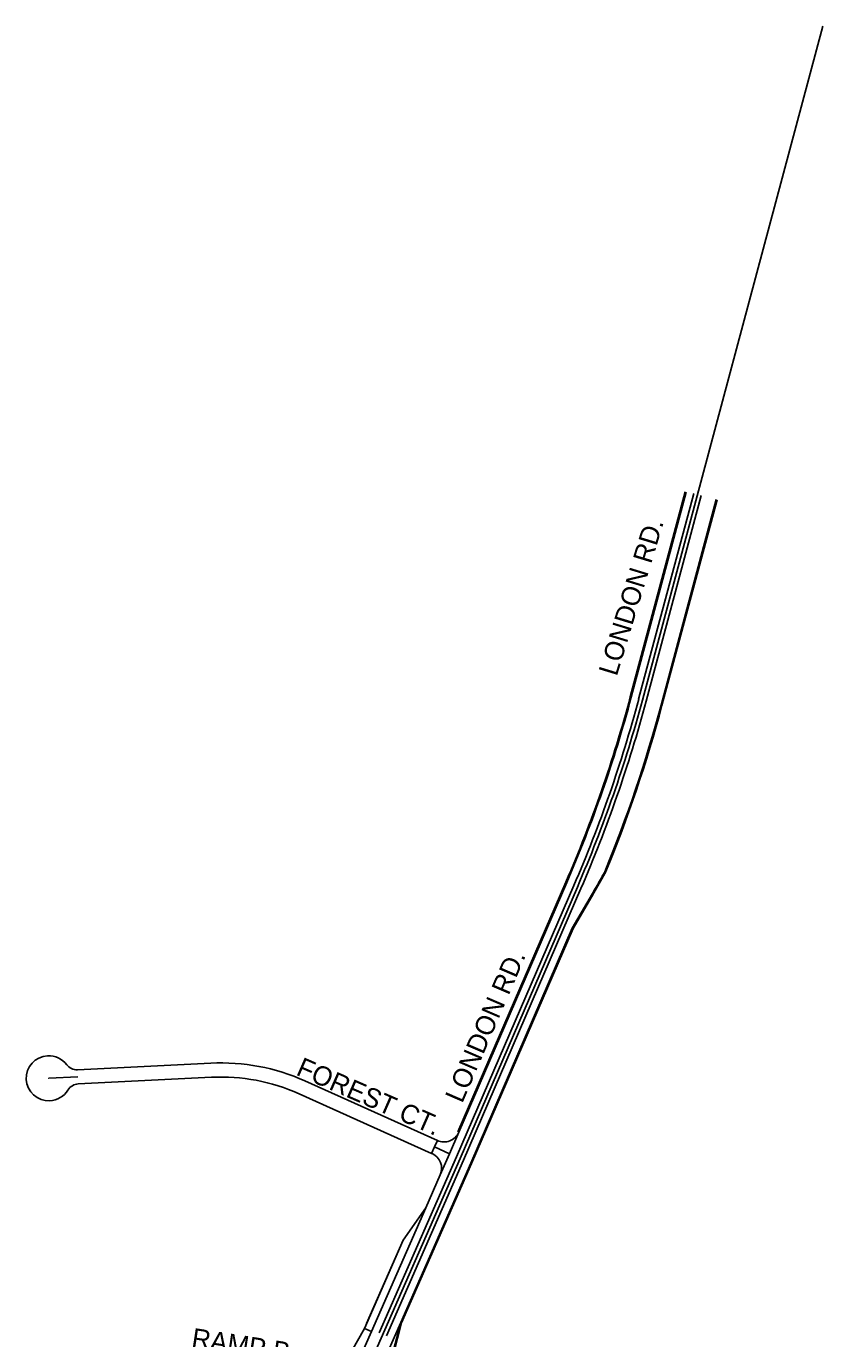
# Model space of a CAD drawing. Extents: x 2315515 to 2326910, y 758186 to 762794.
# Drawn here: x 2320679 to 2321918, y 760752 to 762794 of the extents above; entities that cross this region are included whole.
import ezdxf

# ---------------------------------------------------------------- set-up
doc = ezdxf.new("R2010")
doc.units = 0
for name, color, linetype in [('Default', 7, 'Continuous'), ('Draft_Corr_Range_Design', 7, 'Continuous'), ('E_Terrain_Exterior', 7, 'Continuous'), ('Pavement Marking Yellow', 7, 'Continuous'), ('Road_Curb_Face', 7, 'Continuous'), ('TL_End Condition Ditch In', 7, 'Continuous'), ('TL_End Condition Ditch Out', 7, 'Continuous'), ('TL_Pavement Edge Sub', 7, 'Continuous')]:
    doc.layers.add(name, color=color, linetype=linetype)

msp = doc.modelspace()

# ---------------------------------------------------------------- linework, layer by layer
at = {"layer": 'Default'}
for p, q in [((2321637, 761745.2), (2321917.6, 762793.6)), ((2321637, 761745.2), (2321917.6, 762793.6)), ((2321637, 761745.2), (2321917.6, 762793.6)), ((2321353.4, 761032.3), (2321535.9, 761454.5)), ((2321353.4, 761032.3), (2321535.9, 761454.5)), ((2321353.4, 761032.3), (2321535.9, 761454.5)), ((2320896.6, 759992.2), (2321353.4, 761032.3)), ((2320896.6, 759992.2), (2321353.4, 761032.3)), ((2320896.6, 759992.2), (2321353.4, 761032.3))]:
    msp.add_line(p, q, dxfattribs=at)
msp.add_arc((2319608.4, 762288), 2100, 336.617, 345.0204, dxfattribs=at)
msp.add_arc((2319608.4, 762288), 2100, 336.617, 345.0204, dxfattribs=at)
msp.add_arc((2319608.4, 762288), 2100, 336.617, 345.0204, dxfattribs=at)
msp.add_open_spline([(2321559.3, 761444.4), (2321559.6, 761445), (2321560.3, 761446.1), (2321561.2, 761447.8), (2321562.2, 761449.5), (2321563.2, 761451.2), (2321564.1, 761452.9), (2321565.1, 761454.5), (2321566.1, 761456.2), (2321567, 761457.9), (2321568, 761459.6), (2321569, 761461.3), (2321569.9, 761463), (2321570.9, 761464.7), (2321571.8, 761466.4), (2321572.8, 761468.1), (2321573.7, 761469.7), (2321574.7, 761471.4), (2321575.6, 761473.1), (2321576.6, 761474.8), (2321577.5, 761476.5), (2321578.2, 761477.7), (2321578.5, 761478.2)], degree=3, dxfattribs=at)
at = {"layer": 'Draft_Corr_Range_Design'}
msp.add_line((2321215.5, 760763.1), (2321299.9, 760955.4), dxfattribs=at)
at = {"layer": 'E_Terrain_Exterior'}
for p, q in [((2321619.7, 761749.8), (2321705, 762068.7)), ((2321619.7, 761749.8), (2321705, 762068.7)), ((2321666, 761737.4), (2321751.6, 762057.4)), ((2321666, 761737.4), (2321751.6, 762057.4)), ((2321351.4, 761073.1), (2321519.4, 761461.7)), ((2321351.4, 761073.1), (2321519.4, 761461.7)), ((2321527.9, 761390.6), (2321559.3, 761444.4)), ((2321527.9, 761390.6), (2321559.3, 761444.4)), ((2321369.9, 761025.1), (2321527.9, 761390.6)), ((2321369.9, 761025.1), (2321527.9, 761390.6)), ((2320965.7, 761180.6), (2320758.4, 761170.3)), ((2320965.7, 761180.6), (2320758.4, 761170.3)), ((2320759.5, 761148.3), (2320966.8, 761158.6)), ((2321318.2, 761060.2), (2321112, 761153)), ((2321318.2, 761060.2), (2321112, 761153)), ((2321102.9, 761132.9), (2321309.2, 761040.1)), ((2321313.7, 761050.2), (2321318.2, 761060.2)), ((2321313.7, 761050.2), (2321309.2, 761040.1)), ((2321309.9, 761039.8), (2321309.2, 761040.1)), ((2321261, 760777.3), (2321369.9, 761025.1)), ((2321261, 760777.3), (2321369.9, 761025.1)), ((2321299.9, 760955.4), (2321322.6, 761006.9)), ((2321299.9, 760955.4), (2321322.6, 761006.9)), ((2321264.8, 760905.3), (2321299.9, 760955.4)), ((2321204.5, 760767.9), (2321264.8, 760905.3)), ((2321207.9, 760775.6), (2321264.8, 760905.3)), ((2321248.3, 760728.3), (2321261, 760777.3)), ((2321184.8, 760732.9), (2321204.5, 760767.9))]:
    msp.add_line(p, q, dxfattribs=at)
for centre, radius, start, end in [((2319608.4, 762288), 2082, 336.617, 345.0204), ((2319608.4, 762288), 2082, 336.617, 345.0204), ((2319608.4, 762288), 2130, 337.6565, 345.0204), ((2319608.4, 762288), 2130, 337.6565, 345.0204), ((2320713.6, 761157), 35, 92.8425, 272.8425), ((2320713.6, 761157), 35, 37.1502, 92.8425), ((2320757.4, 761190.2), 20, 217.1502, 272.8425), ((2320757.4, 761190.2), 20, 217.1502, 272.8425), ((2320981.5, 760863), 318, 65.781, 92.8425), ((2320981.5, 760863), 318, 65.781, 92.8425), ((2320760.5, 761128.3), 20, 92.8425, 148.5349), ((2320760.5, 761128.3), 20, 92.8425, 148.5349), ((2320981.5, 760863), 296, 65.781, 92.8425), ((2320713.6, 761157), 35, 272.8425, 328.5349), ((2321328.4, 761083), 25, 245.781, 336.617), ((2321299.7, 761017), 25, 336.2923, 65.781), ((2321299.7, 761017), 25, 336.2923, 65.781)]:
    msp.add_arc(centre, radius, start, end, dxfattribs=at)
msp.add_open_spline([(2321559.3, 761444.4), (2321559.6, 761445), (2321560.3, 761446.1), (2321561.2, 761447.8), (2321562.2, 761449.5), (2321563.2, 761451.2), (2321564.1, 761452.9), (2321565.1, 761454.5), (2321566.1, 761456.2), (2321567, 761457.9), (2321568, 761459.6), (2321569, 761461.3), (2321569.9, 761463), (2321570.9, 761464.7), (2321571.8, 761466.4), (2321572.8, 761468.1), (2321573.7, 761469.7), (2321574.7, 761471.4), (2321575.6, 761473.1), (2321576.6, 761474.8), (2321577.5, 761476.5), (2321578.2, 761477.7), (2321578.5, 761478.2)], degree=3, dxfattribs=at)
at = {"layer": 'Pavement Marking Yellow'}
for p, q in [((2321631.2, 761746.7), (2321716.9, 762066.7)), ((2321642.8, 761743.6), (2321728.5, 762063.6)), ((2321347.9, 761034.7), (2321530.4, 761456.9)), ((2321358.9, 761029.9), (2321541.4, 761452.2)), ((2321227.8, 760761.2), (2321347.9, 761034.7)), ((2321238.8, 760756.5), (2321358.9, 761029.9))]:
    msp.add_line(p, q, dxfattribs=at)
for radius in [2094, 2106]:
    msp.add_arc((2319608.4, 762288), radius, 336.617, 345.0204, dxfattribs=at)
at = {"layer": 'Road_Curb_Face'}
for p, q in [((2321618.2, 761750.2), (2321703.5, 762069.1)), ((2321667.5, 761737), (2321753.1, 762057)), ((2321667.5, 761737), (2321753.1, 762057)), ((2321579.8, 761477.5), (2321579.8, 761477.6)), ((2321350, 761073.7), (2321518, 761462.3)), ((2321529.2, 761389.8), (2321560.6, 761443.7)), ((2321529.2, 761389.9), (2321560.6, 761443.7)), ((2321371.3, 761024.5), (2321529.3, 761390)), ((2321371.3, 761024.5), (2321529.2, 761389.9)), ((2321262.4, 760776.7), (2321371.3, 761024.5)), ((2321262.5, 760776.8), (2321371.3, 761024.5)), ((2321249.7, 760727.9), (2321262.5, 760776.9)), ((2321249.7, 760727.9), (2321262.5, 760776.8))]:
    msp.add_line(p, q, dxfattribs=at)
for radius, start in [(2080.5, 336.617), (2131.5, 337.6542), (2131.5, 337.6565)]:
    msp.add_arc((2319608.4, 762288), radius, start, 345.0204, dxfattribs=at)
msp.add_open_spline([(2321560.6, 761443.7), (2321560.8, 761444), (2321561.4, 761445.1), (2321562.6, 761447.1), (2321563.5, 761448.7), (2321564.5, 761450.4), (2321565.4, 761452.1), (2321566.4, 761453.8), (2321567.4, 761455.5), (2321568.3, 761457.2), (2321569.3, 761458.9), (2321570.3, 761460.6), (2321571.2, 761462.2), (2321572.2, 761463.9), (2321573.1, 761465.6), (2321574.1, 761467.3), (2321575.1, 761469), (2321576, 761470.7), (2321577, 761472.4), (2321577.9, 761474), (2321579, 761476.1), (2321579.6, 761477.2), (2321579.8, 761477.5)], degree=2, dxfattribs=at)
msp.add_open_spline([(2321560.6, 761443.7), (2321560.8, 761444), (2321561.4, 761445.1), (2321562.6, 761447.1), (2321563.5, 761448.7), (2321564.5, 761450.4), (2321565.4, 761452.1), (2321566.4, 761453.8), (2321567.4, 761455.5), (2321568.3, 761457.2), (2321569.3, 761458.9), (2321570.3, 761460.6), (2321571.2, 761462.2), (2321572.2, 761463.9), (2321573.1, 761465.6), (2321574.1, 761467.3), (2321575.1, 761469), (2321576, 761470.7), (2321577, 761472.4), (2321577.9, 761474), (2321579, 761476.1), (2321579.6, 761477.2), (2321579.8, 761477.5)], degree=2, dxfattribs=at)
at = {"layer": 'TL_End Condition Ditch In'}
for p, q in [((2321336.9, 761039.5), (2321351.4, 761073.1)), ((2321313.7, 761050.2), (2321337, 761039.7)), ((2321322.6, 761006.9), (2321336.9, 761039.5)), ((2321196.2, 760629.7), (2321261, 760777.3)), ((2321163, 760643.5), (2321215.5, 760763.1)), ((2321204.5, 760767.9), (2321215.5, 760763.1))]:
    msp.add_line(p, q, dxfattribs=at)
at = {"layer": 'TL_End Condition Ditch Out'}
msp.add_line((2320713.6, 761157), (2320759, 761159.3), dxfattribs=at)
at = {"layer": 'TL_Pavement Edge Sub'}
for radius in [0.0594, 0.0061, 0.00167, 0.00113]:
    msp.add_circle((2320713.6, 761157), radius, dxfattribs=at)

# ---------------------------------------------------------------- texts
at = {"layer": 'Default'}
for s, rotation, p in [('LONDON RD.', 73.0343, (2321597.1, 761781.4)), ('LONDON RD.', 66.7465, (2321356.7, 761117)), ('FOREST CT.', 336.3217, (2321096.7, 761163)), ('RAMP B', 351.3639, (2320934.5, 760739))]:
    msp.add_text(s, height=30, rotation=rotation, dxfattribs=at).set_placement(p)

doc.saveas('drawing.dxf')
